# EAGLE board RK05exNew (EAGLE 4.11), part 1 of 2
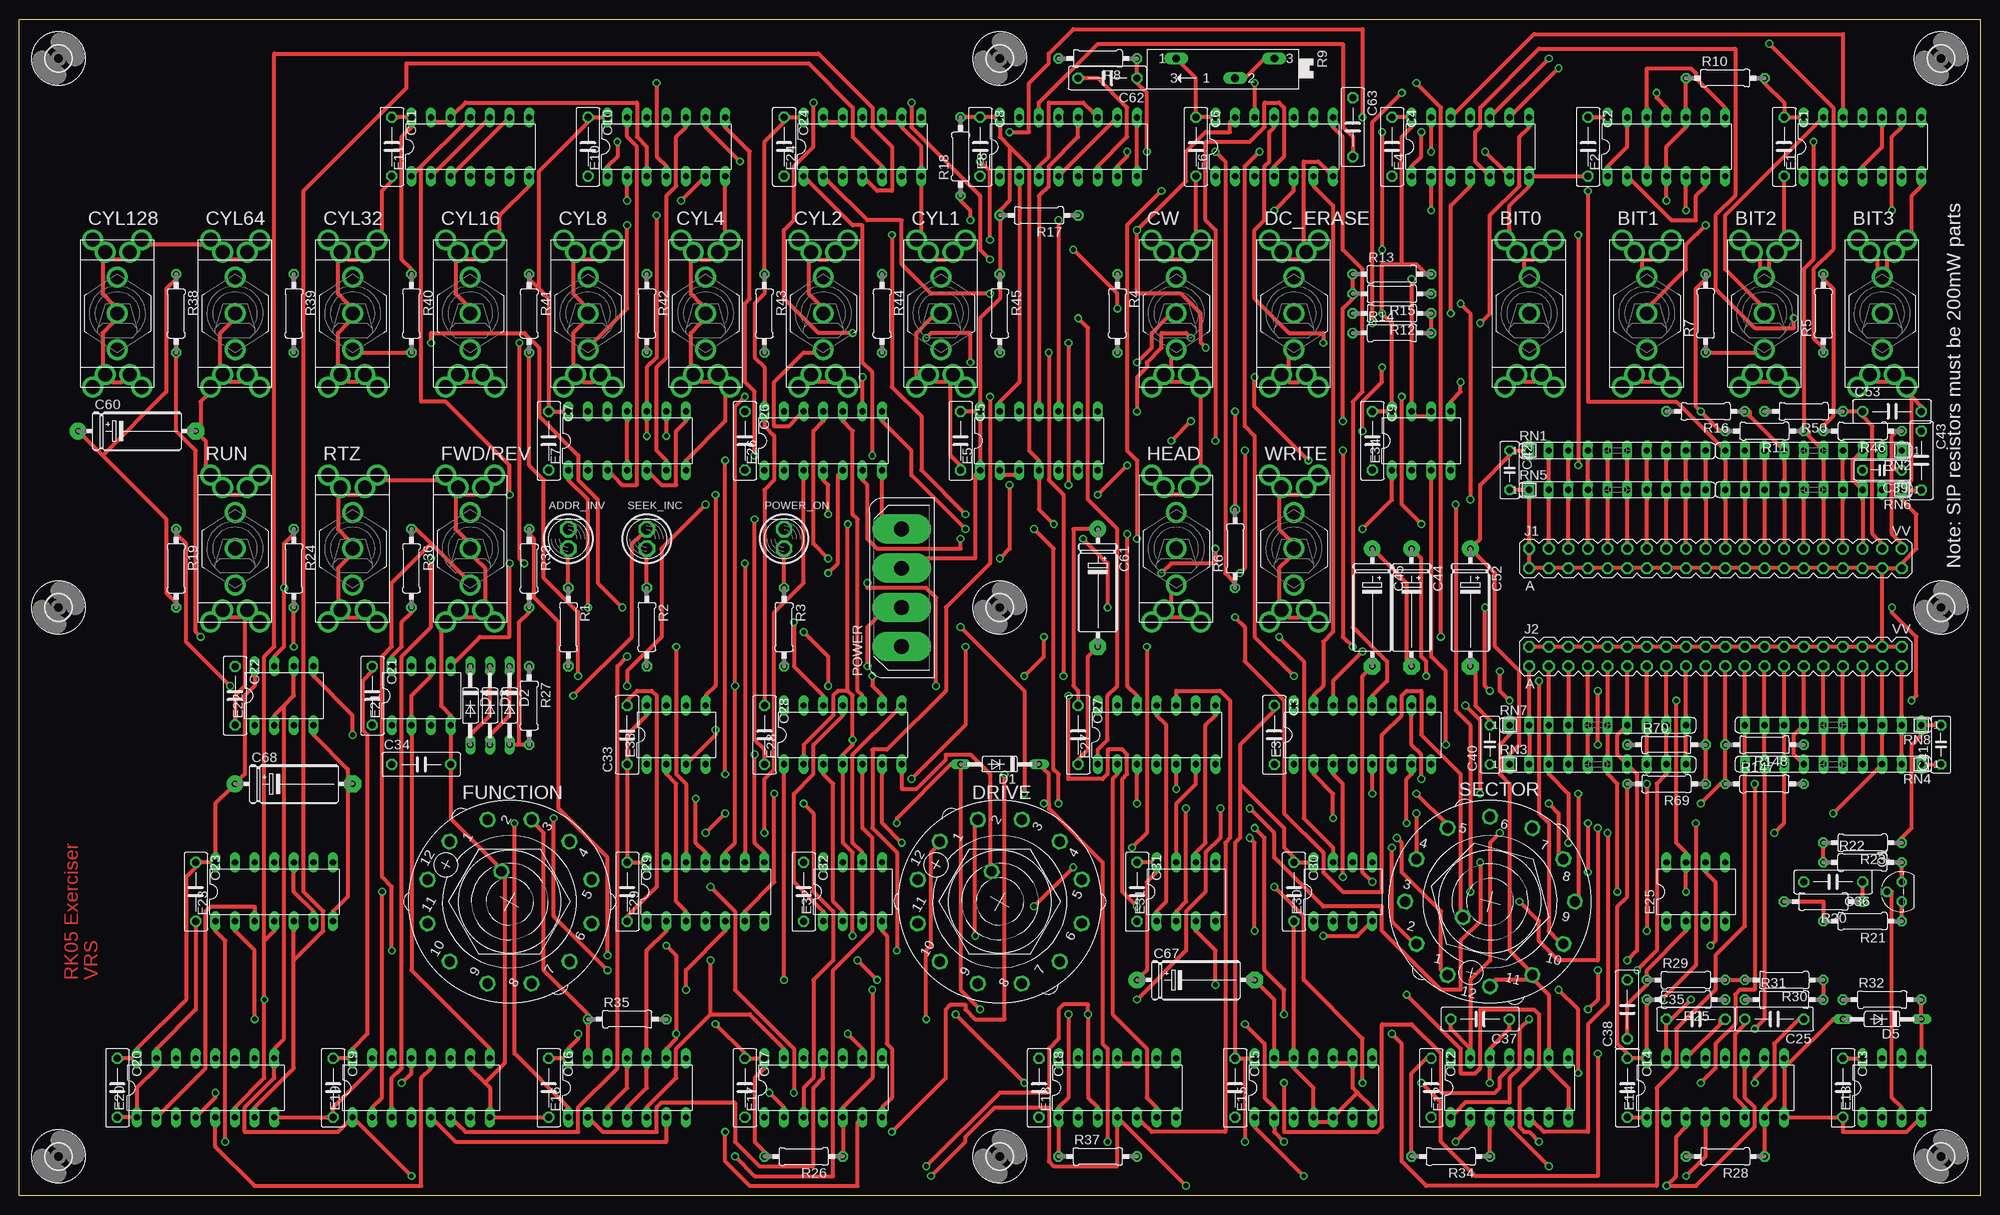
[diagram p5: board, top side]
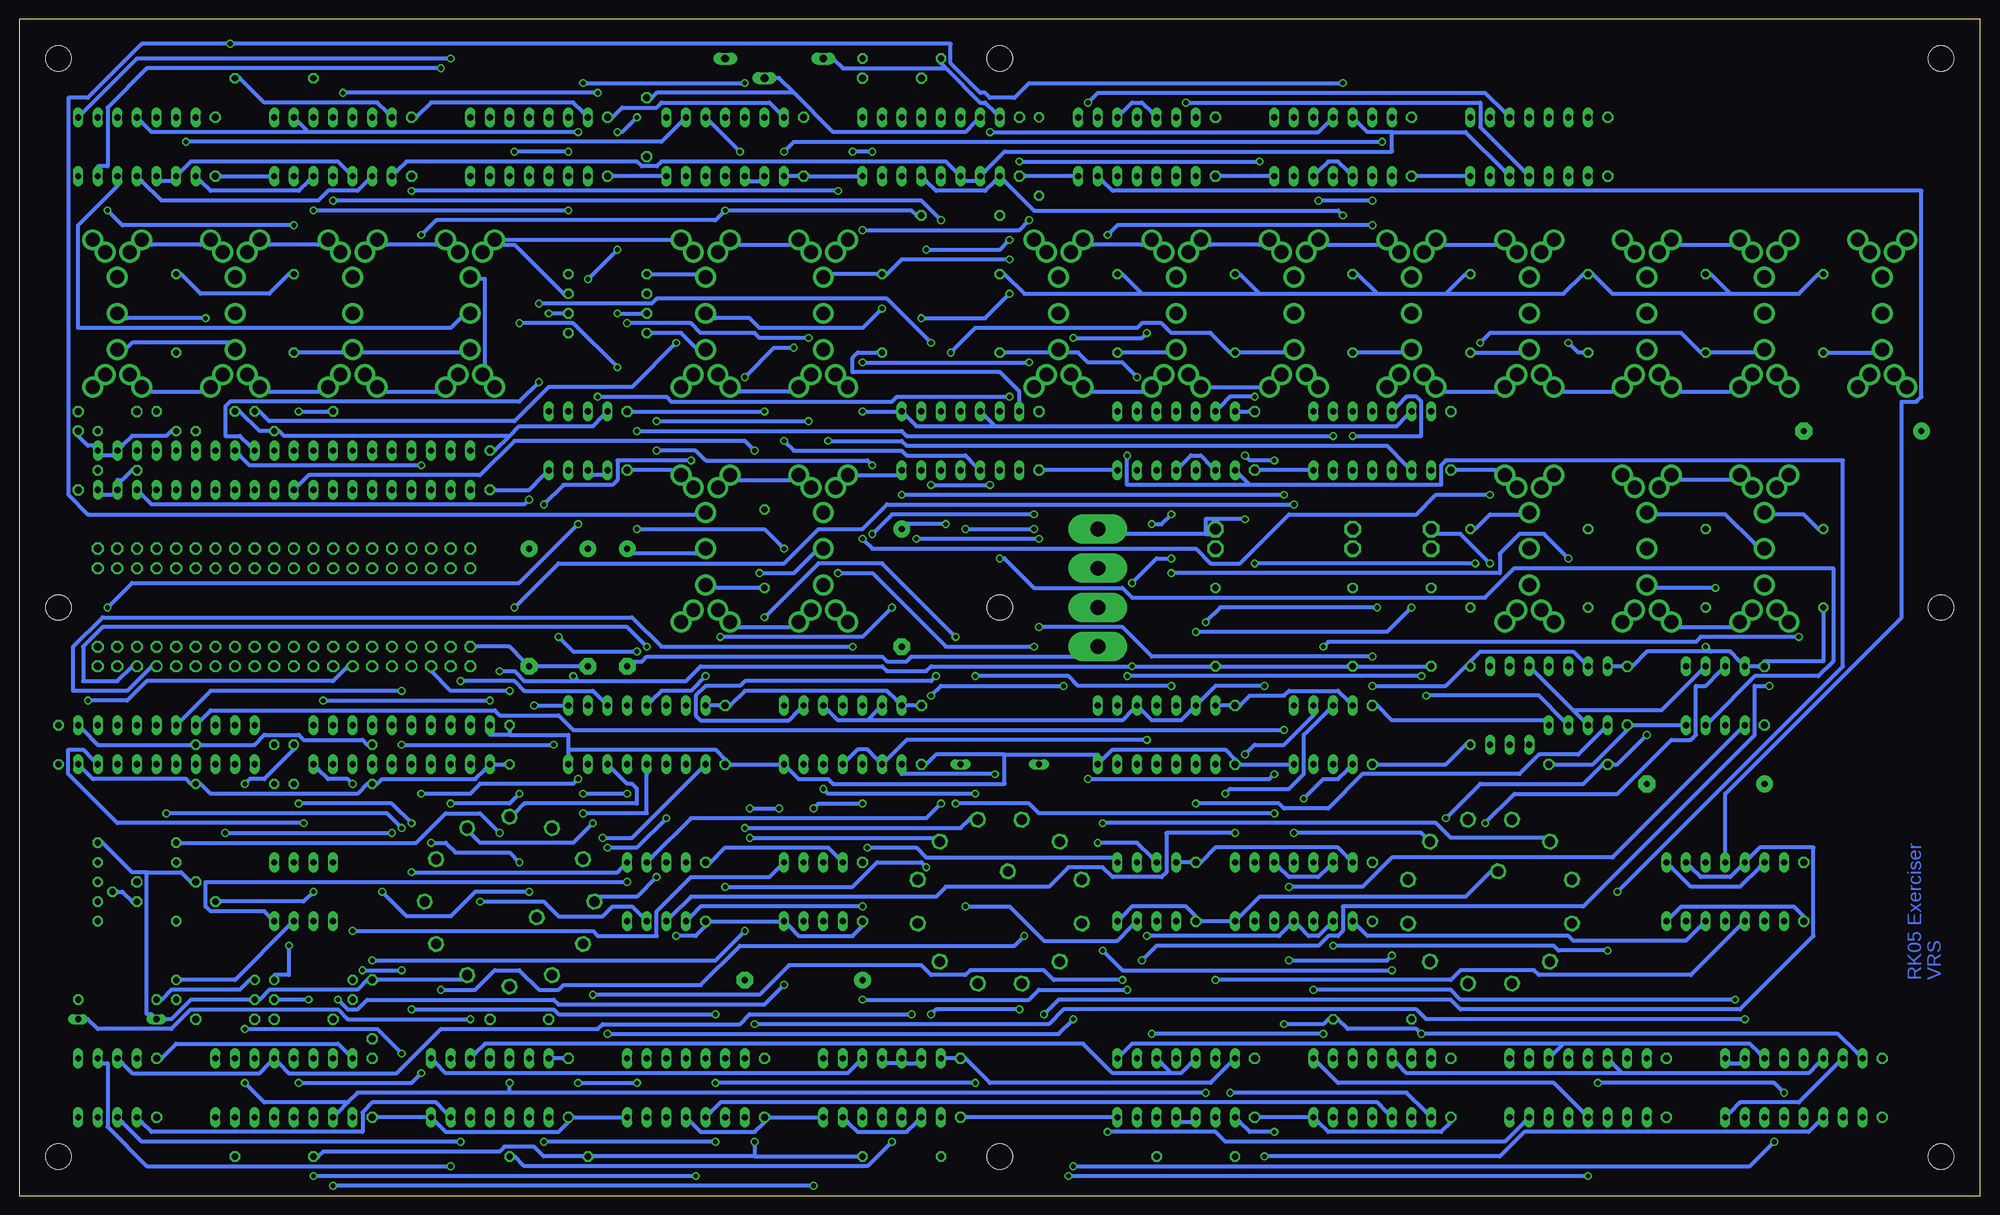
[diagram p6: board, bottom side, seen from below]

Size 254 x 152.4 mm. Coordinates in mm from the lower left corner, seen from the top.
Outline: 0,0 0,152.4 254,152.4 254,0 0,0
Copper layers (1*16): Top 0.035mm / dielectric 1.5mm / Bottom 0.035mm
Design rules "10mils": minimum track width 10mil, minimum drill 24mil, track to track 10mil, track to pad 10mil, pad to pad 10mil, via to via 10mil, smd to smd 0mil, copper to edge 25mil, drill to drill 10mil, minimum pad ring 10mil, minimum via ring 8mil, stop-mask expansion 0mil, vias tented up to drill 0mil, thermal gap 10mil
Net classes: 0 default: width 0.508 mm, drill 0.279 mm

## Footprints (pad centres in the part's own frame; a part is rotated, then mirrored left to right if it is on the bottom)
BULB = drill 1.422 octagon: A 0,0; B 0,2.54
7109MD9V3 = drill 1.803 round: 1 0,4.699; 2 0,0; 3 0,-4.699; NC@1 -3.175,9.525; NC@2 -1.587,7.938; NC@3 3.175,9.525; NC@4 1.587,7.938; NC@5 -3.175,-9.525; NC@6 -1.587,-7.938; NC@7 1.587,-7.938; NC@8 3.175,-9.525
C075-032X103 = drill 0.914 octagon: 1 -3.81,0; 2 3.81,0
C050-025X075 = drill 0.813 octagon: 1 -2.54,0; 2 2.54,0
E15-5 = drill 0.813 pad 2.159 round: + -7.62,0 | drill 0.813 pad 2.159 octagon: - 7.62,0
DO35-10 = drill 0.813 long: A 5.08,0; C -5.08,0
DO35Z10 = drill 0.813 long: A 5.08,0; C -5.08,0
CK101X12 = drill 1.321 octagon: 1 -2.845,-10.617; 2 -7.772,-7.772; 3 -10.617,-2.845; 4 -10.617,2.845; 5 -7.772,7.772; 6 -2.845,10.617; 7 2.845,10.617; 8 7.772,7.772; 9 10.617,2.845; 10 10.617,-2.845; 11 7.772,-7.772; 12 2.845,-10.617; A -2.87,-2.87
DIL14 = drill 0.813 long: 1 -7.62,-3.81; 2 -5.08,-3.81; 3 -2.54,-3.81; 4 0,-3.81; 5 2.54,-3.81; 6 5.08,-3.81; 7 7.62,-3.81; 8 7.62,3.81; 9 5.08,3.81; 10 2.54,3.81; 11 0,3.81; 12 -2.54,3.81; 13 -5.08,3.81; 14 -7.62,3.81
DIL16 = drill 0.813 long: 1 -8.89,-3.81; 2 -6.35,-3.81; 3 -3.81,-3.81; 4 -1.27,-3.81; 5 1.27,-3.81; 6 3.81,-3.81; 7 6.35,-3.81; 8 8.89,-3.81; 9 8.89,3.81; 10 6.35,3.81; 11 3.81,3.81; 12 1.27,3.81; 13 -1.27,3.81; 14 -3.81,3.81; 15 -6.35,3.81; 16 -8.89,3.81
DIL08 = drill 0.813 long: 1 -3.81,-3.81; 2 -1.27,-3.81; 3 1.27,-3.81; 4 3.81,-3.81; 5 3.81,3.81; 6 1.27,3.81; 7 -1.27,3.81; 8 -3.81,3.81
DEC40PINV = drill 1.016 octagon: A -24.13,-1.27; AA 3.81,-1.27; B -24.13,1.27; BB 3.81,1.27; C -21.59,-1.27; CC 6.35,-1.27; D -21.59,1.27; DD 6.35,1.27; E -19.05,-1.27; EE 8.89,-1.27; F -19.05,1.27; FF 8.89,1.27; H -16.51,-1.27; HH 11.43,-1.27; J -16.51,1.27; JJ 11.43,1.27; K -13.97,-1.27; KK 13.97,-1.27; L -13.97,1.27; LL 13.97,1.27; M -11.43,-1.27; MM 16.51,-1.27; N -11.43,1.27; NN 16.51,1.27; P -8.89,-1.27; PP 19.05,-1.27; R -8.89,1.27; RR 19.05,1.27; S -6.35,-1.27; SS 21.59,-1.27; T -6.35,1.27; TT 21.59,1.27; U -3.81,-1.27; UU 24.13,-1.27; V -3.81,1.27; VV 24.13,1.27; W -1.27,-1.27; X -1.27,1.27; Y 1.27,-1.27; Z 1.27,1.27
FLOPPY-4 = drill 1.93 pad 3.81 long: 1 7.62,0; 2 2.54,0; 3 -2.54,0; 4 -7.62,0
TO92E = drill 0.813 octagon: B1 -1.27,0; B2 1.27,0; E 0,1.905
0207/10 = drill 0.813 octagon: 1 -5.08,0; 2 5.08,0
SP19L = drill 1.016 long: A 5.715,-1.27; E -6.985,-1.27; S -1.905,1.27
SIL10 = drill 0.813 long: 1 -11.43,0; 2 -8.89,0; 3 -6.35,0; 4 -3.81,0; 5 -1.27,0; 6 1.27,0; 7 3.81,0; 8 6.35,0; 9 8.89,0; 10 11.43,0
3,3 = hole 3.3: 0,0

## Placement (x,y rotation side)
ADDR_INV  [BULB]  71.12,83.82 0 top
BIT0  7101  [7109MD9V3]  195.58,114.3 0 top
BIT1  7101  [7109MD9V3]  210.82,114.3 0 top
BIT2  7101  [7109MD9V3]  226.06,114.3 0 top
BIT3  7101  [7109MD9V3]  241.3,114.3 0 top
C1  .01uf  [C075-032X103]  228.6,135.89 270 top
C2  .01uf  [C075-032X103]  203.2,135.89 270 top
C3  .01uf  [C075-032X103]  162.56,59.69 270 top
C4  .01uf  [C075-032X103]  177.8,135.89 270 top
C5  .01uf  [C075-032X103]  121.92,97.79 270 top
C6  .01uf  [C075-032X103]  152.4,135.89 270 top
C7  .01uf  [C075-032X103]  68.58,97.79 270 top
C8  .01uf  [C075-032X103]  124.46,135.89 270 top
C9  .01uf  [C075-032X103]  175.26,97.79 270 top
C10  .01uf  [C075-032X103]  73.66,135.89 270 top
C11  .01uf  [C075-032X103]  48.26,135.89 270 top
C12  .01uf  [C075-032X103]  182.88,13.97 270 top
C13  .01uf  [C075-032X103]  236.22,13.97 270 top
C14  .01uf  [C075-032X103]  208.28,13.97 270 top
C15  .01uf  [C075-032X103]  157.48,13.97 270 top
C16  .01uf  [C075-032X103]  68.58,13.97 270 top
C17  .01uf  [C075-032X103]  93.98,13.97 270 top
C18  .01uf  [C075-032X103]  132.08,13.97 270 top
C19  .01uf  [C075-032X103]  40.64,13.97 270 top
C20  .01uf  [C075-032X103]  12.7,13.97 270 top
C21  .01uf  [C075-032X103]  45.72,64.77 270 top
C22  .01uf  [C075-032X103]  27.94,64.77 270 top
C23  .01uf  [C075-032X103]  22.86,39.37 270 top
C24  .01uf  [C075-032X103]  99.06,135.89 270 top
C25  470pf  [C075-032X103]  227.33,22.86 180 top
C26  .01uf  [C075-032X103]  93.98,97.79 270 top
C27  .01uf  [C075-032X103]  137.16,59.69 270 top
C28  .01uf  [C075-032X103]  96.52,59.69 270 top
C29  .01uf  [C075-032X103]  78.74,39.37 270 top
C30  .01uf  [C075-032X103]  165.1,39.37 270 top
C31  .01uf  [C075-032X103]  144.78,39.37 270 top
C32  .01uf  [C075-032X103]  101.6,39.37 270 top
C33  .01uf  [C075-032X103]  78.74,59.69 90 top
C34  .001uf  [C075-032X103]  52.07,55.88 0 top
C35  470pf  [C075-032X103]  217.17,22.86 0 top
C36  .033uf  [C075-032X103]  234.95,40.64 180 top
C37  .001uf  [C075-032X103]  189.23,22.86 180 top
C38  100pf  [C075-032X103]  208.28,24.13 90 top
C39  .001  [C050-025X075]  241.3,93.98 180 top
C40  .22uf  [C050-025X075]  190.5,58.42 90 top
C41  .22uf  [C050-025X075]  248.92,58.42 90 top
C42  .22uf  [C050-025X075]  193.04,93.98 270 top
C43  .22uf  [C075-032X103]  246.38,95.25 270 top
C44  6.8uf  [E15-5]  180.34,76.2 270 top
C45  6.8uf  [E15-5]  175.26,76.2 270 top
C52  39uf  [E15-5]  187.96,76.2 270 top
C53  .001  [C075-032X103]  242.57,101.6 0 top
C60  6.8uf  [E15-5]  15.24,99.06 0 top
C61  6.8uf  [E15-5]  139.7,78.74 270 top
C62  27pf  [C075-032X103]  140.97,144.78 180 top
C63  47pf  [C075-032X103]  172.72,138.43 270 top
C67  6.8uf  [E15-5]  152.4,27.94 0 top
C68  6.8uf  [E15-5]  35.56,53.34 0 top
CW  7101  [7109MD9V3]  149.86,114.3 0 top
CYL1  7101  [7109MD9V3]  119.38,114.3 0 top
CYL2  7101  [7109MD9V3]  104.14,114.3 0 top
CYL4  7101  [7109MD9V3]  88.9,114.3 0 top
CYL8  7101  [7109MD9V3]  73.66,114.3 0 top
CYL16  7101  [7109MD9V3]  58.42,114.3 0 top
CYL32  7101  [7109MD9V3]  43.18,114.3 0 top
CYL64  7101  [7109MD9V3]  27.94,114.3 0 top
CYL128  7101  [7109MD9V3]  12.7,114.3 0 top
D1  D664  [DO35-10]  127,55.88 180 top
D2  D664  [DO35-10]  63.5,63.5 270 top
D3  D664  [DO35-10]  60.96,63.5 270 top
D4  D664  [DO35-10]  58.42,63.5 270 top
D5  1N746  [DO35Z10]  241.3,22.86 180 top
DC_ERASE  7101  [7109MD9V3]  165.1,114.3 0 top
DRIVE  [CK101X12]  127,38.1 240 top
E1  74LS10N  [DIL14]  238.76,135.89 0 top
E2  74LS74N  [DIL14]  213.36,135.89 0 top
E3  74LS42N  [DIL16]  173.99,59.69 0 top
E4  74LS20N  [DIL14]  187.96,135.89 0 top
E5  74LS74N  [DIL14]  132.08,97.79 0 top
E6  74LS04N  [DIL14]  162.56,135.89 0 top
E7  74LS00N  [DIL14]  78.74,97.79 0 top
E8  74123N  [DIL16]  135.89,135.89 0 top
E10  74LS00N  [DIL14]  83.82,135.89 0 top
E11  74LS74N  [DIL14]  58.42,135.89 0 top
E12  74LS04N  [DIL14]  193.04,13.97 0 top
E13  DS75451N  [DIL08]  242.57,13.97 0 top
E14  74123N  [DIL16]  219.71,13.97 0 top
E15  74LS00N  [DIL14]  167.64,13.97 0 top
E16  74LS10N  [DIL14]  78.74,13.97 0 top
E17  74LS00N  [DIL14]  104.14,13.97 0 top
E18  74LS74N  [DIL14]  142.24,13.97 0 top
E19  74LS193N  [DIL16]  52.07,13.97 0 top
E20  74LS193N  [DIL16]  24.13,13.97 0 top
E21  DS75451N  [DIL08]  52.07,64.77 0 top
E22  DS75451N  [DIL08]  34.29,64.77 0 top
E23  74LS10N  [DIL14]  33.02,39.37 0 top
E24  74LS20N  [DIL14]  109.22,135.89 0 top
E25  LM741P  [DIL08]  217.17,39.37 0 top
E26  74LS00N  [DIL14]  104.14,97.79 0 top
E27  74LS00N  [DIL14]  147.32,59.69 0 top
E28  74LS00N  [DIL14]  106.68,59.69 0 top
E29  74LS00N  [DIL14]  88.9,39.37 0 top
E30  DS75451N  [DIL08]  171.45,39.37 0 top
E31  DS75451N  [DIL08]  151.13,39.37 0 top
E32  DS75451N  [DIL08]  107.95,39.37 0 top
E33  DS75451N  [DIL08]  85.09,59.69 0 top
E34  DS75451N  [DIL08]  181.61,97.79 0 top
FUNCTION  [CK101X12]  63.5,38.1 240 top
FWD/REV  7101  [7109MD9V3]  58.42,83.82 0 top
HEAD  7101  [7109MD9V3]  149.86,83.82 0 top
J1  DEC40PINSV  [DEC40PINV]  219.71,82.55 0 top
J2  DEC40PINSV  [DEC40PINV]  219.71,69.85 0 top
POWER  [FLOPPY-4]  114.3,78.74 90 top
POWER_ON  [BULB]  99.06,83.82 0 top
Q1  2N4894  [TO92E]  243.84,39.37 90 top
R1  0ohm  [0207/10]  71.12,73.66 270 top
R2  0ohm  [0207/10]  81.28,73.66 270 top
R3  0ohm  [0207/10]  99.06,73.66 270 top
R4  1K  [0207/10]  142.24,114.3 270 top
R5  56K  [0207/10]  233.68,114.3 90 top
R6  56K  [0207/10]  157.48,83.82 90 top
R7  1K  [0207/10]  218.44,114.3 90 top
R8  5.6k  [0207/10]  139.7,147.32 180 top
R9  10K  [SP19L]  155.57,146.05 180 top
R10  1K  [0207/10]  220.98,144.78 0 top
R11  1K  [0207/10]  226.06,99.06 180 top
R12  330  [0207/10]  177.8,114.3 180 top
R13  330  [0207/10]  177.8,119.38 0 top
R14  750  [0207/10]  177.8,111.76 0 top
R15  750  [0207/10]  177.8,116.84 180 top
R16  1K  [0207/10]  218.44,101.6 180 top
R17  1K  [0207/10]  132.08,127 180 top
R18  1K  [0207/10]  121.92,134.62 90 top
R19  1K  [0207/10]  20.32,81.28 270 top
R20  470K  [0207/10]  233.68,38.1 180 top
R21  330  [0207/10]  238.76,35.56 180 top
R22  120  [0207/10]  238.76,43.18 0 top
R23  68  [0207/10]  238.76,45.72 180 top
R24  1K  [0207/10]  35.56,81.28 270 top
R25  10K  [0207/10]  215.9,25.4 180 top
R26  1K  [0207/10]  101.6,5.08 180 top
R27  1K  [0207/10]  66.04,63.5 270 top
R28  22K  [0207/10]  220.98,5.08 180 top
R29  100K  [0207/10]  215.9,27.94 0 top
R30  100K  [0207/10]  228.6,27.94 180 top
R31  1M  [0207/10]  228.6,25.4 0 top
R32  1K  [0207/10]  241.3,25.4 0 top
R33  1K  [0207/10]  66.04,81.28 270 top
R34  1K  [0207/10]  185.42,5.08 180 top
R35  1K  [0207/10]  78.74,22.86 0 top
R36  1K  [0207/10]  50.8,81.28 270 top
R37  1K  [0207/10]  139.7,5.08 0 top
R38  1K  [0207/10]  20.32,114.3 270 top
R39  1K  [0207/10]  35.56,114.3 270 top
R40  1K  [0207/10]  50.8,114.3 270 top
R41  1K  [0207/10]  66.04,114.3 270 top
R42  1K  [0207/10]  81.28,114.3 270 top
R43  1K  [0207/10]  96.52,114.3 270 top
R44  1K  [0207/10]  111.76,114.3 270 top
R45  1K  [0207/10]  127,114.3 270 top
R46  390  [0207/10]  238.76,99.06 180 top
R50  390  [0207/10]  231.14,101.6 180 top
R69  180  [0207/10]  213.36,53.34 180 top
R70  390  [0207/10]  213.36,58.42 0 top
R147  180  [0207/10]  226.06,53.34 0 top
R148  390  [0207/10]  226.06,58.42 180 top
RN1  180  [SIL10]  207.01,96.52 0 top
RN2  180  [SIL10]  232.41,96.52 180 top
RN3  180  [SIL10]  204.47,55.88 0 top
RN4  180  [SIL10]  234.95,55.88 180 top
RN5  390  [SIL10]  207.01,91.44 0 top
RN6  390  [SIL10]  232.41,91.44 180 top
RN7  390  [SIL10]  204.47,60.96 0 top
RN8  390  [SIL10]  234.95,60.96 180 top
RTZ  7101  [7109MD9V3]  43.18,83.82 0 top
RUN  7101  [7109MD9V3]  27.94,83.82 0 top
SECTOR  [CK101X12]  190.5,38.1 345 top
SEEK_INC  [BULB]  81.28,83.82 0 top
U$1  [3,3]  5.08,147.32 0 top
U$2  [3,3]  5.08,5.08 0 top
U$3  [3,3]  5.08,76.2 0 top
U$4  [3,3]  248.92,147.32 0 top
U$5  [3,3]  248.92,5.08 0 top
U$6  [3,3]  248.92,76.2 0 top
U$7  [3,3]  127,147.32 0 top
U$8  [3,3]  127,5.08 0 top
U$9  [3,3]  127,76.2 0 top
WRITE  7108  [7109MD9V3]  165.1,83.82 0 top

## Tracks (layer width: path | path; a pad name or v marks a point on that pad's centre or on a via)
0BIT  (via drill 0.61)
  Top 0.508: v199.39,146.05 193.68,140.34 E4.9
  Bottom 0.508: v199.39,146.05 237.49,146.05 242.57,140.97 242.57,133.35 243.84,133.35 E1.6
1.44MHZ
  Top 0.508: E5.11 132.08,102.87 132.08,129.54 133.35,130.81 133.35,133.35 137.16,137.16 137.16,138.43 E8.12
1BIT  (via drill 0.61)
  Top 0.508: v198.12,147.32 191.13,140.34 E4.10
  Bottom 0.508: v198.12,147.32 238.76,147.32 245.75,140.34 E1.8
1L  (via drill 0.61)
  Top 0.508: v212.09,142.88 212.09,142.24 213.36,140.97 E2.11 | v179.07,142.88 175.26,139.06 v175.26,113.03 | v151.76,111.12 151.13,111.76 147.96,111.76 147.96,109.86 146.05,107.95 146.05,107.31 144.78,106.05 v144.78,101.6
  Bottom 0.508: 127.64,99.69 75.56,99.69 74.3,100.97 E7.13 | 127.64,99.69 128.91,100.97 E5.12 | 127.64,99.69 137.79,99.69 139.06,100.97 E5.8 140.34,101.6 v144.78,101.6 | v179.07,142.88 v212.09,142.88 | v175.26,113.03 167,113.03 165.74,111.76 158.75,111.76 158.12,111.12 v151.76,111.12
2.88MHZ
  Top 0.508: E8.4 135.25,132.72 141.6,139.06 E8.10
2BIT
  Top 0.508: E4.12 186.06,140.34 196.22,150.5 236.22,150.5 236.22,140.97 E1.12
2H  (via drill 0.61)
  Top 0.508: v181.61,137.79 181.61,134.62 180.34,133.35 E4.1
  Bottom 0.508: v181.61,137.79 216.53,137.79 | 216.53,137.79 217.81,139.06 E2.9 | 216.53,137.79 236.85,137.79 238.12,139.06 E1.11
2L
  Top 0.508: E2.3 210.82,133.35 210.82,138.43 E2.12 210.82,140.97 210.82,146.05 216.53,146.05 217.17,145.41 217.17,144.78 220.98,140.97 E2.8
  Bottom 0.508: E1.3 235.59,131.44 234.31,131.44 E1.2 233.04,132.72 231.78,133.99 212.72,133.99 211.46,132.72 E2.3
3BIT  (via drill 0.61)
  Top 0.508: v182.88,135.25 182.88,138.43 E4.13 | v189.87,135.25 192.41,132.72 E4.6
  Bottom 0.508: v182.88,135.25 v189.87,135.25
4H  (via drill 0.61)
  Top 0.508: v182.88,127.64 182.88,130.81 E4.2 | v215.9,127.64 215.9,130.81 E2.5
  Bottom 0.508: v182.88,127.64 v215.9,127.64 | E1.1 230.5,131.44 229.24,130.18 217.81,130.18 216.53,131.44 E2.5
4L
  Top 0.508: E1.4 238.76,133.35 241.3,135.89 241.3,138.43 E1.10 | E2.2 208.91,131.44 214,126.36 217.17,126.36 217.17,129.54 218.44,130.81 E2.6
  Bottom 0.508: E1.4 238.12,131.44 235.59,128.91 215.26,128.91 214,130.18 210.19,130.18 208.91,131.44 E2.2
202_DETECT_L
  Bottom 0.508: E23.11 33.02,44.45 33.02,52.07 10.16,74.93 10.16,102.87 8.26,102.87 7.62,103.5 7.62,130.18 112.39,130.18 113.67,131.44 E24.6
+3V  (via drill 0.61)
  Top 0.508: 34.29,63.5 35.56,64.77 35.56,67.31 E22.6 | 34.29,63.5 33.02,62.23 E22.2 | E19.9 60.96,19.05 50.8,29.21 50.8,59.69 E21.2 50.8,62.23 50.8,64.77 53.34,67.31 E21.6 | 34.29,63.5 34.29,20.32 33.02,19.05 E20.9 33.02,16.51 33.02,15.24 29.21,11.43 29.21,8.26 41.27,8.26 42.55,9.53 E19.1 43.81,9.53 v50.8,2.54 | v151.13,1.27 142.88,9.53 E18.4 142.24,8.89 142.24,3.81 133.99,3.81 133.35,4.45 133.35,11.43 126.36,11.43 122.56,7.62 122.56,6.99 v118.11,2.54 | E14.3 215.9,8.89 214.63,7.62 214.63,2.54 v213.36,1.27 217.17,1.27 224.79,8.89 224.79,11.43 223.52,12.7 223.52,16.51 E14.11
  Bottom 0.508: E20.10 31.11,17.14 32.38,17.14 E20.9 | 52.7,62.87 51.44,61.59 E21.2 | 52.7,62.87 57.78,67.94 D4.C | 52.7,62.87 41.27,62.87 36.2,67.94 E22.6 | v151.13,1.27 v213.36,1.27 | v50.8,2.54 v118.11,2.54
+3VA  (via drill 0.61)
  Top 0.508: v151.76,100.33 v149.22,97.79 | v171.45,100.33 171.45,114.94 172.72,116.2 R15.2 172.72,117.47 172.72,118.75 R13.1
  Bottom 0.508: v149.22,97.79 139.7,97.79 139.06,97.16 76.83,97.16 74.3,94.61 E7.2 | v171.45,100.33 v151.76,100.33 | DC_ERASE.1 166.37,119.38 172.09,119.38 R13.1
+3VB  (via drill 0.61)
  Top 0.508: R14.2 182.88,112.39 182.88,113.67 R12.1 | v185.42,114.3 185.42,128.27 187.96,130.81 E4.4
  Bottom 0.508: v185.42,114.3 183.51,114.3 R12.1
+3VC  (via drill 0.61)
  Top 0.508: E11.2 53.98,132.72 60.33,139.06 E11.10 | v125.73,121.28 124.46,122.56 124.46,129.54 115.57,138.43 v115.57,141.6
  Bottom 0.508: CW.1 148.59,119.38 142.88,119.38 R4.1 141.6,119.38 139.7,121.28 v125.73,121.28 | v115.57,141.6 114.3,142.88 64.14,142.88 61.59,140.34 E11.10
+15V  (via drill 0.61)
  Top 0.508: R20.2 229.24,38.1 233.68,38.1 233.68,36.2 R21.2 | v215.9,39.37 215.9,41.91 E25.7 215.9,44.45 214.63,45.72 v214.63,64.14 | v182.25,67.31 182.25,69.22 181.61,69.85 181.61,82.55 180.97,83.19 C44.+ | v109.86,68.58 109.86,73.66 111.12,74.93 POWER.3 | v193.04,64.14 191.77,65.41 v191.77,67.94
  Bottom 0.508: v215.9,39.37 217.17,38.1 227.97,38.1 R20.2 | R1.2 71.75,68.58 80.64,68.58 R2.2 81.92,68.58 98.42,68.58 R3.2 99.69,68.58 v109.86,68.58 135.89,68.58 136.53,67.94 141.6,67.94 142.24,68.58 165.74,68.58 167.64,66.67 181.61,66.67 | 181.61,66.67 v182.25,67.31 | v214.63,64.14 v193.04,64.14 | v191.77,67.94 189.87,67.94 188.59,66.67 181.61,66.67
-15V  (via drill 0.61)
  Top 0.508: v175.26,40.64 173.99,41.91 173.99,67.31 174.62,67.94 C45.-
  Bottom 0.508: v175.26,40.64 229.87,40.64 229.87,37.47 229.24,36.83 222.25,36.83 221.62,36.2 E25.4 | POWER.4 117.47,69.85 138.43,69.85 139.06,69.22 141.6,69.22 142.24,69.85 172.72,69.85 173.35,69.22 174.62,69.22 C45.-
ADDR_COUNTER_1  (via drill 0.61)
  Top 0.508: v53.34,82.55 53.34,73.66 49.53,69.85 49.53,16.51 48.26,15.24 48.26,11.43 E19.3 | v104.78,80.64 106.05,81.92 106.05,93.34 E26.5
  Bottom 0.508: v53.34,82.55 56.52,85.72 59.69,85.72 62.23,83.19 62.23,80.64 v104.78,80.64
ADDR_COUNTER_2  (via drill 0.61)
  Top 0.508: v46.99,39.37 46.99,12.7 45.72,11.43 E19.2 | v110.49,95.89 110.49,106.68 109.22,107.95 109.22,125.73 107.95,125.73 102.23,131.44 E24.1
  Bottom 0.508: v46.99,39.37 17.78,68.58 17.78,95.25 69.22,95.25 69.85,94.61 69.85,92.08 94.61,92.08 | 94.61,92.08 95.89,93.34 E26.1 | v110.49,95.89 110.49,92.08 94.61,92.08
ADDR_COUNTER_4  (via drill 0.61)
  Top 0.508: v78.74,69.85 77.47,68.58 77.47,16.51 72.39,11.43 72.39,8.26 57.78,8.26 56.52,9.53 E19.6 | v121.92,73.66 130.18,65.41 v130.18,52.07 | v149.86,52.7 149.86,54.61 E27.5
  Bottom 0.508: v78.74,69.85 107.31,69.85 111.12,73.66 v121.92,73.66 | v130.18,52.07 149.22,52.07 v149.86,52.7
ADDR_COUNTER_8  (via drill 0.61)
  Top 0.508: v113.03,8.26 120.02,15.24 120.02,24.13 120.65,24.77 122.56,24.77 122.56,24.13 123.83,22.86 127.64,22.86 v127.64,54.61 | v125.73,116.84 118.11,116.84 114.3,120.65 114.3,126.36 109.86,126.36 104.78,131.44 E24.2 | v137.16,113.67 138.43,112.39 138.43,90.17 142.24,86.36 142.24,66.04 140.97,64.77 140.97,59.05 139.7,57.78 139.7,57.15 E27.1
  Bottom 0.508: v113.03,8.26 99.06,8.26 97.79,6.99 61.59,6.99 59.05,9.53 E19.7 | v127.64,54.61 139.7,54.61 E27.1 | v125.73,116.84 128.91,113.67 v137.16,113.67
ADDR_COUNTER_16  (via drill 0.61)
  Top 0.508: v92.71,5.08 95.25,2.54 105.41,2.54 105.41,29.21 110.49,34.29 110.49,46.35 109.22,47.62 109.22,54.61 E28.5
  Bottom 0.508: v92.71,5.08 62.23,5.08 59.05,8.26 22.23,8.26 20.95,9.53 E20.3
ADDR_COUNTER_32  (via drill 0.61)
  Top 0.508: E20.2 18.41,10.79 24.13,16.51 24.13,36.83 24.77,37.47 30.48,37.47 30.48,36.83 E23.3 | v99.06,27.94 99.06,54.61 E28.1
  Bottom 0.508: v99.06,27.94 68.58,27.94 67.31,29.21 57.78,29.21 57.15,28.57 37.47,28.57 31.11,34.92 E23.3
ADDR_COUNTER_64  (via drill 0.61)
  Top 0.508: 31.75,33.02 v31.75,25.4 31.75,15.24 27.94,11.43 E20.6 | 31.75,33.02 33.02,34.29 E23.4 | v86.36,26.67 86.36,29.21 91.44,34.29 E29.5 | 31.75,33.02 31.75,69.85 33.02,71.12 33.02,147.96 103.5,147.96 110.49,140.97 110.49,138.43 113.03,135.89 113.03,130.18 111.12,130.18 109.86,131.44 E24.4
  Bottom 0.508: v86.36,26.67 68.58,26.67 67.31,25.4 v31.75,25.4
ADDR_COUNTER_128
  Top 0.508: 35.56,30.48 35.56,34.29 E23.5 | 35.56,30.48 35.56,16.51 30.48,11.43 E20.7 | 35.56,30.48 39.37,34.29 39.37,36.83 36.83,39.37 36.83,130.18 50.16,143.51 50.16,146.69 102.23,146.69 107.95,140.97 107.95,137.16 111.76,133.35 E24.5
  Bottom 0.508: E29.1 80.64,34.92 79.38,33.66 53.34,33.66 52.7,33.02 38.1,33.02 36.2,34.92 E23.5
ADDR_SOURCE_H  (via drill 0.61)
  Top 0.508: v93.98,103.5 92.71,102.23 v92.71,66.04 92.71,45.72 91.44,44.45 E29.10 | E26.10 106.68,100.33 107.95,99.06 107.95,88.27 108.58,87.63 108.58,65.41 109.22,64.77 E28.10 | E18.5 145.41,9.53 146.69,8.26 156.21,8.26 156.21,45.72 156.84,46.35 156.84,64.14 155.57,65.41 149.86,65.41 149.86,64.77 E27.10
  Bottom 0.508: E29.13 84.45,42.55 85.72,41.27 89.53,41.27 90.81,42.55 E29.10 | v93.98,103.5 97.16,103.5 98.42,102.23 E26.13 | 144.15,61.59 142.88,62.87 E27.13 | 144.15,61.59 147.96,61.59 149.22,62.87 E27.10 | 144.15,61.59 111.12,61.59 109.86,62.87 E28.10 108.58,62.87 107.31,61.59 103.5,61.59 102.23,62.87 E28.13 100.97,64.14 99.06,66.04 v92.71,66.04
ADDR_SOURCE_L  (via drill 0.61)
  Top 0.508: E27.2 142.24,54.61 141.6,53.98 141.6,23.5 146.05,19.05 146.05,12.7 147.32,11.43 E18.6 | E16.4 78.74,11.43 81.28,13.97 81.28,16.51 E16.10 81.28,19.05 81.28,31.75 83.82,34.29 E29.2 | 107.31,65.41 106.05,65.41 105.41,64.77 105.41,62.23 101.6,58.42 101.6,57.15 E28.2 | 107.31,65.41 107.95,64.77 v107.95,59.05 107.95,58.42 106.68,57.15 E28.4 106.68,54.61 106.68,45.72 107.95,44.45 v107.95,33.66 | v104.78,88.27 104.78,92.08 104.14,92.71 E26.4 | 107.31,65.41 v107.31,87
  Bottom 0.508: E27.4 146.69,56.52 145.41,57.78 144.15,57.78 142.88,56.52 E27.2 141.6,56.52 139.06,59.05 v107.95,59.05 | E18.2 137.79,9.53 139.06,8.26 145.41,8.26 146.69,9.53 E18.6 | E29.2 84.45,34.92 85.72,33.66 87,33.66 88.27,34.92 E29.4 89.53,34.92 90.81,33.66 v107.95,33.66 | E26.2 99.69,94.61 100.97,95.89 102.23,95.89 103.5,94.61 E26.4 | v104.78,88.27 106.05,87 v107.31,87
ADDRESS_INVALID_L  (via drill 0.61)
  Top 0.508: v63.5,81.92 63.5,72.39 59.69,72.39 56.52,69.22 E21.5
  Bottom 0.508: v63.5,81.92 67.31,85.72 70.48,85.72 ADDR_INV.B
BIT_0L
  Bottom 0.508: E1.5 241.3,130.81 246.38,125.73 246.38,112.39 198.12,112.39 196.85,113.67 BIT0.2
BIT_1L  (via drill 0.61)
  Top 0.508: v242.57,127.64 242.57,137.16 243.84,138.43 E1.9 | v218.44,125.73 215.9,123.19 215.9,120.02 211.46,115.57 BIT1.2
  Bottom 0.508: v242.57,127.64 240.66,125.73 v218.44,125.73
BIT_2L
  Top 0.508: E1.13 233.04,139.06 220.98,127 220.98,120.02 225.43,115.57 BIT2.2
BIT_3L  (via drill 0.61)
  Top 0.508: v229.87,113.67 229.87,112.39 224.79,112.39 219.71,117.47 219.71,127 222.25,129.54 222.25,148.59 196.85,148.59 189.23,140.97 189.23,138.43 188.59,137.79 188.59,133.99 189.87,132.72 E4.5
  Bottom 0.508: v229.87,113.67 240.03,113.67 BIT3.2
BUS_AC_LO_L
  Top 0.508: 242.57,94.61 243.21,93.98 C39.1 | 242.57,94.61 242.57,98.42 243.21,99.06 R46.1 | 242.57,94.61 242.57,85.72 243.84,84.45 J1.VV
BUS_ADDR_ACCEPTED_L
  Top 0.508: RN3.5 203.2,57.15 203.2,59.69 RN7.5 203.2,62.23 203.2,67.94 J2.H
BUS_ADDRESS_INVALID_L  (via drill 0.61)
  Top 0.508: R26.1 106.68,5.71 106.68,8.89 E17.5 106.68,11.43 110.49,15.24 v110.49,26.67 | J2.C 198.12,67.94 198.12,62.23 RN7.3 198.12,59.69 198.12,57.15 RN3.3 198.12,54.61 200.66,52.07 v200.66,45.72 | v144.78,25.4 151.13,31.75 151.13,36.83 153.67,39.37 153.67,44.45 155.57,46.35 v155.57,50.16 | v159.38,50.16 162.56,46.99 162.56,43.81 168.91,37.47 176.53,37.47 176.53,34.29 184.15,26.67 186.69,26.67 186.69,33.02 189.23,35.56 v189.23,43.18
  Bottom 0.508: v110.49,26.67 121.92,26.67 123.19,25.4 v144.78,25.4 | v159.38,50.16 v155.57,50.16 | v189.23,43.18 190.5,44.45 197.49,44.45 198.75,45.72 v200.66,45.72
BUS_CA_00_L  (via drill 0.61)
  Top 0.508: v203.2,48.26 v203.2,41.91 | v217.81,50.8 220.34,53.34 R147.1 220.98,53.98 220.98,57.78 R148.2 220.98,59.05 220.98,67.94 J2.Y
  Bottom 0.508: v203.2,41.91 176.53,41.91 175.9,42.55 E30.5 | v203.2,48.26 205.74,50.8 v217.81,50.8
BUS_CA_01_L  (via drill 0.61)
  Top 0.508: v194.31,38.1 196.85,35.56 196.85,33.02 199.39,30.48 204.47,30.48 v204.47,47.62 | v234.95,49.53 240.66,55.24 RN4.3 241.3,57.15 241.3,59.69 RN8.3 241.3,62.23 241.3,67.94 J2.SS
  Bottom 0.508: v194.31,38.1 186.06,38.1 184.15,36.2 178.44,36.2 177.16,37.47 174.62,37.47 173.35,36.2 E30.3 | v204.47,47.62 206.38,49.53 v234.95,49.53
BUS_CA_02_L  (via drill 0.61)
  Top 0.508: v210.82,53.34 v210.82,34.29 | RN3.10 215.9,57.15 215.9,59.69 RN7.10 215.9,62.23 215.9,67.94 J2.U
  Bottom 0.508: v210.82,34.29 179.71,34.29 179.07,33.66 171.45,33.66 171.45,36.83 167,41.27 156.84,41.27 155.57,42.55 E31.5 | v210.82,53.34 211.46,53.98 214,53.98 215.26,55.24 RN3.10
BUS_CA_03_L  (via drill 0.61)
  Top 0.508: v154.94,27.3 154.94,31.75 152.4,34.29 E31.3 | v212.72,25.4 217.17,29.84 v217.17,48.26 | RN4.2 243.84,57.15 243.84,59.69 RN8.2 243.84,62.23 243.84,67.94 J2.UU
  Bottom 0.508: v154.94,27.3 157.48,24.77 184.15,24.77 184.78,25.4 208.91,25.4 210.19,24.13 211.46,24.13 v212.72,25.4 | v217.17,48.26 241.3,48.26 247.65,54.61 247.65,57.78 245.75,57.78 244.47,56.52 RN4.2
BUS_CA_04_L  (via drill 0.61)
  Top 0.508: RN4.5 236.22,57.15 236.22,59.69 RN8.5 236.22,62.23 236.22,67.94 J2.MM | v144.15,45.09 146.05,46.99 v146.05,71.12
  Bottom 0.508: v144.15,45.09 137.79,45.09 136.53,43.81 112.39,43.81 E32.5 | v146.05,71.12 170.81,71.12 174.62,74.93 243.21,74.93 247.01,71.12 247.01,65.41 240.03,65.41 236.85,68.58 J2.MM
BUS_CA_05_L  (via drill 0.61)
  Top 0.508: v136.53,42.55 v131.44,37.47 | v162.56,40.01 166.37,36.2 166.37,27.94 173.99,20.32 v173.99,14.61 | v181.61,14.61 184.15,12.06 184.15,6.99 188.59,2.54 204.47,2.54 v204.47,18.41 | v224.79,21.59 226.06,22.86 226.06,54.61 RN4.9 226.06,57.15 226.06,59.69 RN8.9 226.06,62.23 226.06,67.94 J2.CC
  Bottom 0.508: v131.44,37.47 125.73,37.47 121.28,33.02 111.76,33.02 109.86,34.92 E32.3 | v136.53,42.55 137.16,43.18 142.88,43.18 146.05,40.01 v162.56,40.01 | v181.61,14.61 v173.99,14.61 | v204.47,18.41 207.65,21.59 v224.79,21.59
BUS_CA_06_L  (via drill 0.61)
  Top 0.508: RN4.4 238.76,57.15 238.76,59.69 RN8.4 238.76,62.23 238.76,67.94 J2.PP | v90.17,90.81 90.17,66.04 88.9,64.77 E33.5 | v143.51,94.61 v139.7,90.81 | v171.45,96.52 171.45,72.39 v172.72,71.12
  Bottom 0.508: v139.7,90.81 v90.17,90.81 | v143.51,94.61 144.15,95.25 165.1,95.25 166.37,96.52 v171.45,96.52 | v172.72,71.12 175.26,73.66 243.21,73.66 245.75,71.12 245.75,66.67 241.3,66.67 239.4,68.58 J2.PP
BUS_CA_07_L  (via drill 0.61)
  Top 0.508: v90.17,60.33 90.17,59.69 87,56.52 E33.3 | RN4.7 230.5,56.52 229.87,57.15 229.87,59.69 230.5,60.33 RN8.7 231.14,62.23 231.14,67.94 J2.HH
  Bottom 0.508: v90.17,60.33 182.25,60.33 184.15,62.23 191.77,62.23 192.41,62.87 229.24,62.87 230.5,61.59 RN8.7
BUS_DATA&CLOCK_L  (via drill 0.61)
  Top 0.508: RN4.6 233.68,57.15 233.68,59.69 RN8.6 233.68,62.23 233.68,67.94 J2.KK | v184.78,58.42 184.78,67.94 182.88,69.85 182.88,92.71 E34.3 | v204.47,58.42 v204.47,65.41
  Bottom 0.508: v204.47,58.42 v184.78,58.42 | v204.47,65.41 229.24,65.41 233.04,61.59 RN8.6
BUS_DC_LO_L
  Top 0.508: R50.1 236.85,101.6 238.12,101.6 C53.1 238.76,100.97 240.03,99.69 240.03,85.72 241.3,84.45 J1.TT
BUS_FILE_READY
  Top 0.508: RN1.9 215.9,95.25 215.9,92.71 RN5.9 215.9,90.17 215.9,84.45 J1.V
BUS_HIGH_DENSITY_L
  Top 0.508: RN1.6 208.28,95.25 208.28,92.71 RN5.6 208.28,90.17 208.28,84.45 J1.N
BUS_INDEX_L  (via drill 0.61)
  Top 0.508: J1.Z 220.98,84.45 220.98,90.17 RN6.10 220.98,92.71 220.98,95.25 RN2.10 220.34,97.16 214.63,102.87 203.2,102.87 v203.2,130.18 | 52.07,133.35 57.78,139.06 E11.11 | 52.07,133.35 51.44,132.72 E11.1 | v147.96,130.18 143.51,125.73 143.51,96.52 144.78,95.25 v144.78,85.09 | v63.5,90.81 63.5,94.61 55.24,102.87 52.07,102.87 52.07,133.35
  Bottom 0.508: v147.96,130.18 v203.2,130.18 | v144.78,85.09 143.51,83.82 101.6,83.82 99.69,81.92 95.89,81.92 89.53,88.27 73.03,88.27 70.48,90.81 v63.5,90.81
BUS_READ_GATE_L
  Top 0.508: RN1.5 205.74,95.25 205.74,92.71 RN5.5 205.74,90.17 205.74,84.45 J1.L
BUS_RESTORE_L  (via drill 0.61)
  Top 0.508: RN3.8 210.82,57.15 210.82,59.69 RN7.8 210.82,62.23 210.82,67.94 J2.P | v43.18,59.69 43.18,62.23 38.1,67.31 E22.5 | v245.11,64.14 245.75,64.77 245.75,72.39 242.57,75.56 v242.57,76.2 | v181.61,87 179.07,89.53 v179.07,103.5 | v125.73,103.5 125.73,81.92 120.02,76.2 120.02,65.41 112.39,57.78 110.49,57.78 110.49,47.62 113.67,44.45 v113.67,31.75 | v76.2,29.21 69.22,36.2 v69.22,48.9
  Bottom 0.508: v43.18,59.69 46.99,55.88 47.62,55.88 C34.1 48.9,55.88 51.44,53.34 64.77,53.34 v69.22,48.9 | v245.11,64.14 240.03,64.14 237.49,66.67 213.36,66.67 211.46,68.58 J2.P | v242.57,76.2 239.4,79.38 189.23,79.38 v181.61,87 | v179.07,103.5 170.18,103.5 169.54,102.87 140.97,102.87 140.34,103.5 v125.73,103.5 | v113.67,31.75 111.12,29.21 v76.2,29.21
BUS_RWS_READY_L  (via drill 0.61)
  Top 0.508: v205.74,46.99 205.74,24.77 203.2,22.23 203.2,8.26 197.49,8.26 196.22,9.53 E12.5 | v227.33,46.99 228.6,48.26 228.6,54.61 RN4.8 228.6,57.15 228.6,59.69 RN8.8 228.6,62.23 228.6,67.94 J2.EE
  Bottom 0.508: v227.33,46.99 v205.74,46.99
BUS_SECTOR_ADDR_0L  (via drill 0.61)
  Top 0.508: RN2.8 226.06,95.25 226.06,92.71 RN6.8 226.06,90.17 226.06,84.45 J1.DD | v162.56,127.64 165.1,130.18 165.1,130.81 E6.5 | v201.93,124.46 v201.93,94.61
  Bottom 0.508: R17.1 137.79,127 138.43,127.64 v162.56,127.64 163.83,126.36 200.03,126.36 v201.93,124.46 | v201.93,94.61 224.16,94.61 225.43,95.89 RN2.8
BUS_SECTOR_ADDR_1L  (via drill 0.61)
  Top 0.508: J2.K 205.74,67.94 205.74,62.23 RN7.6 205.74,59.69 205.74,57.15 RN3.6 205.74,54.61 207.01,53.34 v207.01,39.37 | v123.19,126.36 123.19,127.64 121.92,128.91 R18.1 | E6.13 156.84,139.06 156.84,137.79 153.67,137.79 151.13,135.25 151.13,131.44 v144.78,125.09 144.78,116.84 150.5,116.84 153.03,114.3 153.03,110.49 v153.67,109.86 | v187.96,39.37 187.96,60.96 186.06,62.87 v186.06,89.53 | v167,95.25 160.02,102.23 v160.02,106.05
  Bottom 0.508: v123.19,126.36 124.46,125.09 v144.78,125.09 | v207.01,39.37 203.84,36.2 198.12,36.2 194.94,39.37 v187.96,39.37 | v186.06,89.53 183.51,92.08 177.16,92.08 176.53,92.71 176.53,95.25 v167,95.25 | v160.02,106.05 156.21,109.86 v153.67,109.86
BUS_SECTOR_ADDR_2L  (via drill 0.61)
  Top 0.508: J1.FF 228.6,84.45 228.6,90.17 RN6.7 228.6,92.71 228.6,95.25 RN2.7 227.97,97.16 224.16,100.97 224.16,101.6 R16.1 | v168.91,110.49 168.91,111.76 164.47,111.76 160.02,116.2 160.02,125.09 161.29,126.36 161.29,133.35 161.93,133.99 161.93,137.79 162.56,138.43 E6.11
  Bottom 0.508: v168.91,110.49 174.62,104.78 185.42,104.78 189.87,100.33 221.62,100.33 222.88,101.6 R16.1
BUS_SECTOR_ADDR_3L  (via drill 0.61)
  Top 0.508: J1.LL 233.68,84.45 233.68,90.17 RN6.5 233.68,92.71 233.68,95.25 RN2.5 233.04,97.16 231.78,98.42 231.78,99.06 R11.1 231.14,99.69 231.14,120.02 232.41,121.28 v232.41,136.53
  Bottom 0.508: v232.41,136.53 170.81,136.53 168.28,139.06 E6.9
BUS_SECTOR_PULSE_L
  Top 0.508: RN1.8 213.36,95.25 213.36,92.71 RN5.8 213.36,90.17 213.36,84.45 J1.T
BUS_SEEK_INCOMPLETE_L  (via drill 0.61)
  Top 0.508: RN3.4 200.66,57.15 200.66,59.69 RN7.4 200.66,62.23 200.66,67.94 J2.E | v190.5,65.41 189.87,66.04 v189.87,76.2 | v88.9,89.53 83.19,83.82 83.19,72.39 78.74,67.94 v78.74,66.04
  Bottom 0.508: E21.7 51.44,69.22 52.7,70.48 64.77,70.48 66.04,69.22 R27.1 66.67,68.58 69.22,66.04 v78.74,66.04 | v190.5,65.41 198.12,65.41 200.66,67.94 J2.E | v189.87,76.2 184.15,81.92 154.94,81.92 150.5,86.36 144.78,86.36 141.6,89.53 v88.9,89.53
BUS_STROBE_L  (via drill 0.61)
  Top 0.508: v127,82.55 128.27,83.82 v128.27,92.08 | v135.89,110.49 v135.89,92.08 | v186.69,115.57 187.96,114.3 v187.96,90.17 | RN2.3 238.12,95.89 237.49,95.25 237.49,92.71 238.12,92.08 RN6.3 238.76,90.17 238.76,84.45 J1.RR
  Bottom 0.508: v127,82.55 126.36,82.55 122.56,78.74 111.12,78.74 109.86,77.47 64.14,77.47 60.33,81.28 19.05,81.28 19.05,69.22 20.95,67.31 29.21,67.31 34.92,61.59 E22.3 | v135.89,92.08 v128.27,92.08 | v135.89,110.49 141.6,116.2 171.45,116.2 172.09,115.57 v186.69,115.57 | v187.96,90.17 188.59,89.53 236.85,89.53 238.12,90.81 RN6.3
BUS_WP_SET_L
  Top 0.508: RN1.4 203.2,95.25 203.2,92.71 RN5.4 203.2,90.17 203.2,84.45 J1.J
BUS_WP_STATUS_L
  Top 0.508: RN1.7 210.82,95.25 210.82,92.71 RN5.7 210.82,90.17 210.82,84.45 J1.R
BUS_WRITE_CK
  Top 0.508: RN2.6 231.14,95.25 231.14,92.71 RN6.6 231.14,90.17 231.14,84.45 J1.JJ
BUS_WRITE_GATE_L  (via drill 0.61)
  Top 0.508: RN2.9 223.52,95.25 223.52,92.71 RN6.9 223.52,90.17 223.52,84.45 J1.BB | v186.69,105.41 186.69,104.14 185.42,102.87 E34.5
  Bottom 0.508: v186.69,105.41 189.23,102.87 226.69,102.87 227.33,102.23 227.33,98.42 225.43,98.42 224.16,97.16 RN2.9
CA_SW_1  (via drill 0.61)
  Top 0.508: v109.22,106.05 109.22,102.87 E26.9
  Bottom 0.508: v109.22,106.05 111.12,107.95 115.57,107.95 116.84,109.22 118.11,109.22 CYL1.3 120.65,109.22 126.36,109.22 R45.2
CA_SW_2
  Top 0.508: E26.12 100.97,100.97 99.69,99.69 97.79,99.69 97.79,105.41 101.6,109.22 102.87,109.22 CYL2.3
  Bottom 0.508: R44.2 111.12,109.22 105.41,109.22 CYL2.3
CA_SW_4  (via drill 0.61)
  Top 0.508: v135.25,67.31 135.25,90.81 133.35,92.71 v133.35,109.22
  Bottom 0.508: CYL4.3 90.17,109.22 95.89,109.22 R43.2 97.16,109.22 99.69,111.76 104.78,111.76 106.05,113.03 108.58,113.03 109.22,112.39 130.18,112.39 v133.35,109.22 | v135.25,67.31 135.89,66.67 160.02,66.67 160.66,66.04 165.1,66.04 166.37,64.77 166.37,62.23 165.74,61.59 154.31,61.59 153.03,62.87 E27.9
CA_SW_8  (via drill 0.61)
  Top 0.508: v143.51,85.72 143.51,66.04 144.78,64.77 E27.12 | v122.56,88.27 116.84,93.98 116.84,100.97 113.03,104.78 v113.03,124.46 | v78.74,125.73 78.74,114.94 74.3,110.49 CYL8.3
  Bottom 0.508: R42.2 80.64,109.22 74.93,109.22 CYL8.3 | v143.51,85.72 140.97,88.27 v122.56,88.27 | v113.03,124.46 111.76,125.73 v78.74,125.73
CA_SW_16  (via drill 0.61)
  Top 0.508: v110.49,67.31 110.49,66.04 111.76,64.77 E28.9 | v72.39,67.31 72.39,75.56 67.94,80.01 67.94,92.71 66.04,94.61 66.04,108.58 R41.2
  Bottom 0.508: R41.2 65.41,109.22 59.69,109.22 CYL16.3 | v72.39,67.31 v110.49,67.31
CA_SW_32  (via drill 0.61)
  Top 0.508: R40.2 50.16,109.22 44.45,109.22 CYL32.3 | v100.33,74.3 100.33,68.58 104.14,64.77 E28.12 | v78.11,76.2 74.93,79.38 74.93,90.17 72.39,92.71 72.39,95.89 67.31,100.97 67.31,109.86 65.41,111.76 53.34,111.76 v53.34,110.49
  Bottom 0.508: v100.33,74.3 98.42,76.2 v78.11,76.2 | v53.34,110.49 52.07,109.22 51.44,109.22 R40.2
CA_SW_64  (via drill 0.61)
  Top 0.508: v93.98,81.92 93.98,44.45 E29.9 | v65.41,81.92 64.77,82.55 v64.77,110.49
  Bottom 0.508: v65.41,81.92 v93.98,81.92 | v64.77,110.49 63.5,111.76 38.73,111.76 36.2,109.22 R39.2 34.92,109.22 29.21,109.22 CYL64.3
CA_SW_128  (via drill 0.61)
  Top 0.508: v85.09,71.12 85.09,54.61 86.36,53.34 86.36,44.45 E29.12 | v23.5,72.39 22.86,73.03 22.86,96.52 20.32,99.06 20.32,108.58 R38.2
  Bottom 0.508: R38.2 19.68,109.22 13.97,109.22 CYL128.3 | v85.09,71.12 84.45,71.75 36.83,71.75 36.2,72.39 v23.5,72.39
CLOCK_H  (via drill 0.61)
  Top 0.508: v81.28,98.42 81.28,100.33 E7.10 81.28,102.87 81.28,107.31 82.55,108.58 v82.55,127
  Bottom 0.508: v81.28,98.42 72.39,98.42 72.39,102.87 73.03,103.5 74.3,103.5 75.56,102.23 E7.12 | E8.5 136.53,131.44 135.25,130.18 128.91,130.18 127.64,131.44 E8.1 126.36,131.44 122.56,127.64 83.19,127.64 v82.55,127
CONSTANT_WRITE_L  (via drill 0.61)
  Top 0.508: v102.87,141.6 102.87,135.89 100.33,133.35 100.33,126.36 99.06,125.09 99.06,116.2 103.5,111.76 v107.95,111.76 | v117.47,111.12 118.11,111.76 123.19,111.76 v123.19,107.95 | v144.78,107.95 146.69,109.86 146.69,111.76 148.59,113.67 CW.2
  Bottom 0.508: v102.87,141.6 64.77,141.6 64.77,138.43 59.05,132.72 E11.4 | v107.95,111.76 108.58,111.12 v117.47,111.12 | v144.78,107.95 v123.19,107.95
DATA_BITS
  Top 0.508: BIT2.3 224.79,109.22 219.07,109.22 R7.1
  Bottom 0.508: R7.1 217.81,109.22 212.09,109.22 BIT1.3 209.55,109.22 196.85,109.22 BIT0.3 | BIT3.3 240.03,109.86 239.4,110.49 226.69,110.49 BIT2.3
DC_ERASE  (via drill 0.61)
  Top 0.508: v93.34,133.99 88.9,138.43 E10.9 | v124.46,133.99 125.73,132.72 v125.73,123.83 | v136.53,122.56 142.24,116.84 v142.24,114.94
  Bottom 0.508: v124.46,133.99 v93.34,133.99 | v125.73,123.83 127,122.56 v136.53,122.56 | v142.24,114.94 144.78,112.39 158.12,112.39 159.38,113.67 163.83,113.67 DC_ERASE.2
FWD_L  (via drill 0.61)
  Top 0.508: 53.34,84.45 57.78,80.01 FWD/REV.3 | 53.34,84.45 51.44,86.36 R36.1 | v107.31,20.95 109.22,19.05 E17.9 | E16.9 83.82,19.05 85.09,20.32 v85.09,20.95 85.09,31.11 v83.82,32.38 | 53.34,84.45 48.26,79.38 48.26,71.12 46.99,69.85 46.99,41.27 48.26,40.01 v48.26,31.75
  Bottom 0.508: v85.09,20.95 v107.31,20.95 | v48.26,31.75 54.61,31.75 55.24,32.38 v83.82,32.38
GND  (via drill 0.61)
  Top 0.508: CYL16.NC@5 55.88,105.41 CYL16.NC@6 57.78,105.41 59.05,105.41 CYL16.NC@7 60.33,105.41 CYL16.NC@8 | CYL32.NC@8 45.09,105.41 CYL32.NC@7 43.81,105.41 42.55,105.41 CYL32.NC@6 | CYL32.NC@5 40.64,105.41 CYL32.NC@6 | CYL32.NC@6 41.27,107.31 41.27,111.76 42.55,113.03 CYL32.2 42.55,115.57 41.27,116.84 41.27,121.28 CYL32.NC@2 | CYL128.NC@8 14.61,105.41 CYL128.NC@7 13.34,105.41 12.06,105.41 CYL128.NC@6 | CYL128.NC@5 10.16,105.41 CYL128.NC@6 | CYL128.NC@6 10.79,107.31 10.79,111.76 12.06,113.03 CYL128.2 12.06,115.57 10.79,116.84 10.79,121.28 CYL128.NC@2 | CYL32.NC@2 40.64,122.56 CYL32.NC@1 | C11.2 48.26,131.44 46.99,130.18 46.99,125.09 CYL32.NC@3 45.72,122.56 CYL32.NC@4 43.81,121.28 42.55,121.28 CYL32.NC@2 | CYL128.NC@2 10.16,122.56 CYL128.NC@1 | CYL128.NC@2 12.06,121.28 13.34,121.28 CYL128.NC@4 15.24,122.56 CYL128.NC@3 17.14,123.19 23.5,123.19 CYL64.NC@1 25.4,122.56 CYL64.NC@2 27.3,121.28 28.57,121.28 CYL64.NC@4 30.48,122.56 CYL64.NC@3 | E26.7 111.76,92.71 111.76,87.63 POWER.1 | CYL1.NC@8 121.28,105.41 CYL1.NC@7 | CYL1.2 118.11,113.67 116.2,111.76 116.2,106.05 CYL1.NC@5 116.84,105.41 CYL1.NC@6 118.75,105.41 120.02,105.41 CYL1.NC@7 | CYL4.NC@5 86.36,105.41 CYL4.NC@6 | CYL4.NC@6 87,107.31 87,111.76 88.27,113.03 CYL4.2 88.27,115.57 87,116.84 87,121.28 CYL4.NC@2 | CYL2.NC@5 101.6,105.41 CYL2.NC@6 103.5,105.41 104.78,105.41 CYL2.NC@7 106.05,105.41 CYL2.NC@8 | E7.7 86.36,95.25 91.44,100.33 91.44,103.5 CYL4.NC@8 90.81,105.41 CYL4.NC@7 89.53,105.41 88.27,105.41 CYL4.NC@6 | C5.2 121.92,94.61 120.65,95.89 120.65,105.41 CYL1.NC@7 | CYL2.NC@3 106.68,122.56 CYL2.NC@4 104.78,121.28 103.5,121.28 CYL2.NC@2
  Top 0.508: CYL2.NC@2 101.6,122.56 CYL2.NC@1 | CYL2.2 103.5,115.57 102.23,116.84 102.23,121.28 CYL2.NC@2 | CYL1.NC@3 121.92,122.56 CYL1.NC@4 120.02,121.28 118.75,121.28 CYL1.NC@2 116.84,122.56 CYL1.NC@1 116.84,125.09 116.84,130.81 E24.7 116.84,133.35 116.84,135.89 114.3,138.43 E24.9 113.67,139.06 112.39,139.06 E24.10 | E24.13 104.78,139.06 106.05,139.06 E24.12 | CYL4.NC@2 86.36,122.56 CYL4.NC@1 | E10.7 91.44,130.81 91.44,125.09 CYL4.NC@3 91.44,122.56 CYL4.NC@4 89.53,121.28 88.27,121.28 CYL4.NC@2 | CYL8.NC@8 75.56,105.41 CYL8.NC@7 74.3,105.41 73.03,105.41 CYL8.NC@6 | CYL8.NC@5 71.12,105.41 CYL8.NC@6 | CYL8.NC@6 71.75,107.31 71.75,111.76 73.03,113.03 CYL8.2 73.03,115.57 71.75,116.84 71.75,121.28 CYL8.NC@2 | CYL16.NC@2 55.88,122.56 CYL16.NC@1 | CYL16.2 57.78,115.57 56.52,116.84 56.52,121.28 CYL16.NC@2 | CYL8.NC@2 71.12,122.56 CYL8.NC@1 | CYL8.NC@3 76.2,122.56 CYL8.NC@4 74.3,121.28 73.03,121.28 CYL8.NC@2 | E11.7 66.04,130.81 62.23,127 62.23,125.09 CYL16.NC@3 60.96,122.56 CYL16.NC@4 59.05,121.28 57.78,121.28 CYL16.NC@2 | E20.8 33.66,10.16 40.01,10.16 C19.2 40.64,10.79 40.64,11.43 45.72,16.51 E19.15 | C20.2 13.34,10.16 14.61,10.16 E20.1 15.24,11.43 15.24,13.97 17.78,16.51 E20.15 17.78,19.05 22.86,24.13 22.86,34.92 C23.2 | E23.7 40.64,36.83 42.55,38.73 42.55,52.7 C68.- 42.55,53.98 42.55,55.24 38.1,59.69 E22.4 | E32.4 111.76,34.29 112.39,33.66 112.39,19.68 113.03,19.05 113.03,12.7 111.76,11.43 E17.7 | 60.33,14.61 60.96,13.97 60.96,11.43 E19.8 61.59,10.16 67.94,10.16 C16.2 | 60.33,14.61 58.42,16.51 E19.10 | C29.2 78.74,36.2 82.55,40.01 82.55,64.77 81.92,65.41 80.01,65.41 78.74,64.14 C33.2
  Top 0.508: RUN.NC@5 25.4,74.93 RUN.NC@6 27.3,74.93 28.57,74.93 RUN.NC@7 | C22.2 27.94,61.59 27.94,64.77 29.21,66.04 29.21,74.93 RUN.NC@7 | RUN.NC@8 29.84,74.93 RUN.NC@7 | FWD/REV.NC@8 60.33,74.93 FWD/REV.NC@7 | FWD/REV.NC@7 60.33,76.83 60.33,81.28 59.05,82.55 FWD/REV.2 57.78,85.09 56.52,86.36 56.52,90.81 FWD/REV.NC@2 | FWD/REV.NC@7 59.05,74.93 57.78,74.93 FWD/REV.NC@6 55.88,74.93 FWD/REV.NC@5 54.61,73.03 54.61,63.5 55.88,62.23 E21.4 55.88,59.69 55.88,56.52 C34.2 55.88,55.24 55.88,48.9 62.23,42.55 FUNCTION.A 62.87,41.27 62.87,17.14 60.33,14.61 | RTZ.NC@8 45.09,74.93 RTZ.NC@7 43.81,74.93 42.55,74.93 RTZ.NC@6 | RTZ.NC@5 40.64,74.93 RTZ.NC@6 | RTZ.NC@6 41.27,76.83 41.27,81.28 42.55,82.55 RTZ.2 42.55,85.09 41.27,86.36 41.27,90.81 RTZ.NC@2 | CYL64.NC@8 29.84,105.41 CYL64.NC@7 28.57,105.41 27.3,105.41 CYL64.NC@6 | CYL64.NC@6 25.4,105.41 CYL64.NC@5 24.13,103.5 23.5,102.87 23.5,99.69 C60.- 23.5,98.42 24.13,97.79 24.13,94.61 RUN.NC@1 25.4,92.08 RUN.NC@2 27.3,90.81 28.57,90.81 RUN.NC@4 30.48,92.08 RUN.NC@3 | CYL64.2 27.3,113.03 26.04,111.76 26.04,107.31 CYL64.NC@6 | FWD/REV.NC@2 55.88,92.08 FWD/REV.NC@1 53.98,92.71 47.62,92.71 RTZ.NC@3 45.72,92.08 RTZ.NC@4 43.81,90.81 42.55,90.81 RTZ.NC@2 | FWD/REV.NC@3 60.96,92.08 FWD/REV.NC@4 59.05,90.81 57.78,90.81 FWD/REV.NC@2 | RTZ.NC@2 40.64,92.08 RTZ.NC@1 | v168.91,33.66 173.35,33.66 174.62,34.92 E30.4 | E15.12 164.47,17.14 163.19,17.14 E15.13 162.56,19.05 162.56,25.4 160.66,27.3 C67.- | E15.10 170.81,17.14 172.09,17.14 E15.9 172.72,16.51 172.72,13.97 173.35,13.34 | 173.35,13.34 175.26,11.43 E15.7 | 173.35,13.34 170.81,10.79 E15.5 169.54,9.53 168.28,9.53 E15.4 167.64,11.43 167.64,13.97 165.1,16.51 E15.12
  Top 0.508: C30.2 165.1,34.92 165.1,19.05 E15.12 | C41.2 248.28,60.96 247.01,60.96 RN8.1 246.38,59.69 245.11,58.42 245.11,47.62 243.84,46.35 R23.1 | E14.1 210.19,10.16 208.91,10.16 C14.2 | E12.7 200.66,11.43 200.66,13.97 198.12,16.51 E12.9 198.12,19.05 198.12,26.04 196.22,27.94 SECTOR.11 | SECTOR.12 191.13,27.94 195.58,27.94 SECTOR.11 | E13.4 245.75,9.53 244.47,8.26 236.22,8.26 236.22,9.53 C13.2 235.59,10.16 229.24,10.16 E14.8 228.6,11.43 228.6,16.51 E14.9 229.24,17.14 234.95,22.86 D5.A | BIT3.NC@5 238.76,105.41 BIT3.NC@6 240.66,105.41 241.94,105.41 BIT3.NC@7 243.21,105.41 BIT3.NC@8 | C43.2 245.75,91.44 244.47,91.44 RN6.1 | 245.11,103.5 246.38,102.23 C53.2 | 245.11,103.5 BIT3.NC@8 | 245.11,103.5 245.11,92.71 244.47,92.08 RN6.1 | 245.11,103.5 BIT3.NC@8 | BIT2.NC@5 223.52,105.41 BIT2.NC@6 225.43,105.41 226.69,105.41 BIT2.NC@7 227.97,105.41 BIT2.NC@8 | BIT0.NC@5 193.04,105.41 BIT0.NC@6 194.94,105.41 196.22,105.41 BIT0.NC@7 197.49,105.41 BIT0.NC@8 | BIT1.NC@5 208.28,105.41 BIT1.NC@6 210.19,105.41 211.46,105.41 BIT1.NC@7 212.72,105.41 BIT1.NC@8 | CW.NC@1 147.32,122.56 CW.NC@2 149.22,121.28 150.5,121.28 CW.NC@4 152.4,122.56 CW.NC@3 152.4,125.09 152.4,131.44 C6.2 | E8.8 144.78,133.35 144.78,138.43 E8.9 | DC_ERASE.NC@1 162.56,122.56 DC_ERASE.NC@2 164.47,121.28 165.74,121.28 DC_ERASE.NC@4 | E6.7 169.54,132.72 168.28,133.99 166.37,133.99 166.37,123.19 DC_ERASE.NC@4 | DC_ERASE.NC@3 167.64,122.56 DC_ERASE.NC@4 | BIT0.NC@3 198.12,122.56 BIT0.NC@4 196.22,121.28 194.94,121.28 | C2.2 202.56,132.08 196.22,132.08 E4.7 195.58,130.81 193.04,128.27 193.04,125.09 BIT0.NC@1 193.04,122.56 BIT0.NC@2
  Top 0.508: 194.94,121.28 194.94,120.02 BIT0.1 | 194.94,121.28 BIT0.NC@2 | 194.94,121.28 BIT0.NC@2 | BIT3.NC@1 238.76,122.56 BIT3.NC@2 240.66,121.28 240.66,120.02 BIT3.1 241.94,120.02 241.94,121.28 BIT3.NC@4 243.84,122.56 BIT3.NC@3 245.11,125.09 245.11,129.54 246.38,130.81 E1.7 | BIT1.NC@3 213.36,122.56 BIT1.NC@4 211.46,121.28 210.19,121.28 | BIT1.NC@2 208.28,122.56 BIT1.NC@1 | 210.19,121.28 210.19,120.02 BIT1.1 | BIT1.NC@2 210.19,121.28 | BIT1.NC@2 210.19,121.28 | BIT2.NC@1 223.52,122.56 BIT2.NC@2 225.43,121.28 225.43,120.02 BIT2.1 226.69,120.02 226.69,121.28 BIT2.NC@4 228.6,122.56 BIT2.NC@3 228.6,125.09 228.6,131.44 C1.2 | C27.2 137.16,56.52 138.43,57.78 138.43,69.85 139.06,70.48 C61.- | DRIVE.A 125.73,42.55 125.73,54.61 123.19,57.15 120.02,57.15 120.02,56.52 116.2,52.7 114.3,52.7 114.3,54.61 E28.7 | WRITE.NC@5 162.56,74.93 WRITE.NC@6 | WRITE.NC@8 167,74.93 WRITE.NC@7 165.74,74.93 164.47,74.93 WRITE.NC@6 | HEAD.NC@8 151.76,74.93 HEAD.NC@7 150.5,74.93 149.22,74.93 HEAD.NC@6 | HEAD.NC@5 147.32,74.93 HEAD.NC@6 | HEAD.3 149.22,78.11 149.22,76.83 HEAD.NC@6 | WRITE.NC@6 163.19,76.83 163.19,81.28 164.47,82.55 WRITE.2 164.47,85.09 163.19,86.36 163.19,90.81 WRITE.NC@2 | CW.NC@5 147.32,105.41 CW.NC@6 | CW.3 149.22,108.58 149.22,107.31 CW.NC@6 | CW.NC@6 149.22,105.41 150.5,105.41 CW.NC@7 151.76,105.41 CW.NC@8 153.03,103.5 153.03,94.61 HEAD.NC@3 152.4,92.08 HEAD.NC@4 150.5,90.81 149.22,90.81 HEAD.NC@2 147.32,92.08 HEAD.NC@1 | DC_ERASE.NC@5 162.56,105.41 DC_ERASE.NC@6 | DC_ERASE.NC@8 167,105.41 DC_ERASE.NC@7 165.74,105.41 164.47,105.41 DC_ERASE.NC@6 | DC_ERASE.3 164.47,108.58 164.47,107.31 DC_ERASE.NC@6
  Top 0.508: WRITE.NC@2 162.56,92.08 WRITE.NC@1 | WRITE.NC@3 167.64,92.08 WRITE.NC@4 165.74,90.81 164.47,90.81 WRITE.NC@2 | C42.2 193.68,91.44 194.94,91.44 RN5.1 195.58,90.17 195.58,84.45 J1.B 195.58,83.19 195.58,81.92 J1.A 196.22,81.28 197.49,81.28 J1.C 198.75,81.28 200.03,81.28 J1.E 201.29,81.28 202.56,81.28 J1.H 203.84,81.28 205.1,81.28 J1.K 206.38,81.28 207.65,81.28 J1.M 208.91,81.28 210.19,81.28 J1.P 211.46,81.28 212.72,81.28 J1.S 214,81.28 215.26,81.28 J1.U 216.53,81.28 217.81,81.28 J1.W 219.07,81.28 220.34,81.28 J1.Y 221.62,81.28 222.88,81.28 J1.AA 224.16,81.28 225.43,81.28 J1.CC 226.69,81.28 227.97,81.28 J1.EE 229.24,81.28 230.5,81.28 J1.HH 231.78,81.28 233.04,81.28 J1.KK 234.31,81.28 235.59,81.28 J1.MM 236.85,81.28 238.12,81.28 J1.PP 239.4,81.28 240.66,81.28 J1.SS | J1.SS 241.94,81.28 243.21,81.28 J1.UU 243.84,81.92 245.75,83.82 245.75,88.27 243.84,90.17 RN6.1 | J2.B 196.22,71.12 197.49,71.12 J2.D 198.75,71.12 200.03,71.12 J2.F 201.29,71.12 202.56,71.12 J2.J 203.84,71.12 205.1,71.12 J2.L 206.38,71.12 207.65,71.12 J2.N 208.91,71.12 210.19,71.12 J2.R 211.46,71.12 212.72,71.12 J2.T 214,71.12 215.26,71.12 J2.V 216.53,71.12 217.81,71.12 J2.X 219.07,71.12 220.34,71.12 J2.Z 221.62,71.12 222.88,71.12 J2.BB 224.16,71.12 225.43,71.12 J2.DD 226.69,71.12 227.97,71.12 J2.FF 229.24,71.12 230.5,71.12 J2.JJ 231.78,71.12 233.04,71.12 J2.LL 234.31,71.12 235.59,71.12 J2.NN 236.85,71.12 238.12,71.12 J2.RR 239.4,71.12 240.66,71.12 J2.TT | J2.VV 243.21,71.12 241.94,71.12 J2.TT | C40.2 190.5,61.59 188.59,63.5 188.59,67.94 C52.-
  Top 0.508: J1.SS 241.3,80.64 241.3,71.75 J2.TT | C45.+ 175.9,83.19 179.71,79.38 179.71,69.22 C44.- | SECTOR.11 195.58,29.21 193.04,31.75 193.04,53.34 191.77,54.61 191.77,58.42 193.04,59.69 RN7.1 | v95.25,87.63 95.25,59.05 96.52,57.78 96.52,56.52 C28.2
  Bottom 0.508: CYL16.NC@5 53.98,104.14 47.62,104.14 CYL32.NC@8 | CYL32.NC@1 38.73,123.19 32.38,123.19 CYL64.NC@3 | C5.2 121.28,93.98 112.39,93.98 E26.7 | 100.33,85.72 111.12,85.72 POWER.1 | 100.33,85.72 99.69,85.72 POWER_ON.B | E7.7 87,93.98 93.34,93.98 C26.2 | CYL2.NC@5 99.69,104.78 93.34,104.78 CYL4.NC@8 | CYL1.NC@5 114.94,104.14 108.58,104.14 CYL2.NC@8 | E24.12 107.31,140.34 108.58,141.6 109.86,141.6 111.12,140.34 E24.10 | C8.2 123.83,132.08 117.47,132.08 E24.7 | CYL2.NC@3 108.58,123.19 114.94,123.19 CYL1.NC@1 | C24.2 98.42,132.08 92.08,132.08 E10.7 | E11.7 66.67,132.08 73.03,132.08 C10.2 | CYL8.NC@1 69.22,123.19 62.87,123.19 CYL16.NC@3 | CYL4.NC@1 84.45,123.19 78.11,123.19 CYL8.NC@3 | CYL2.NC@1 99.69,123.19 93.34,123.19 CYL4.NC@3 | CYL16.NC@8 62.87,104.14 69.22,104.14 CYL8.NC@5 | E22.4 38.73,60.96 45.09,60.96 C21.2 45.72,60.33 50.16,55.88 55.24,55.88 C34.2 | C23.2 22.86,36.2 24.13,37.47 38.73,37.47 40.01,36.2 E23.7 | E20.8 32.38,10.79 31.11,12.06 23.5,12.06 18.41,17.14 E20.15 | E32.4 111.12,36.2 109.86,37.47 102.87,37.47 101.6,36.2 C32.2 100.97,35.56 97.16,35.56 E29.7 95.89,36.2 93.34,38.73 66.67,38.73 63.5,41.91 FUNCTION.A | E17.7 112.39,10.16 131.44,10.16 C18.2 | C17.2 93.34,10.16 87,10.16 E16.7 85.72,9.53 84.45,8.26 69.85,8.26 68.58,9.53 C16.2 | C7.2 67.94,93.98 62.87,93.98 FWD/REV.NC@3 | RTZ.NC@1 38.73,92.71 32.38,92.71 RUN.NC@3 | RUN.NC@8 32.38,73.66 38.73,73.66 RTZ.NC@5 | C33.2 78.11,63.5 76.2,61.59 56.52,61.59 E21.4 | CYL32.NC@5 38.73,104.14 32.38,104.14 CYL64.NC@8 | v168.91,33.66 166.37,33.66 165.1,34.92 C30.2 164.47,35.56 155.57,35.56 E31.4 154.31,34.92 153.03,33.66 146.05,33.66 144.78,34.92 C31.2
  Bottom 0.508: E18.7 150.5,10.16 156.84,10.16 C15.2 157.48,9.53 158.75,8.26 165.74,8.26 167,9.53 E15.4 | E15.7 175.9,10.16 182.25,10.16 C12.2 182.88,9.53 184.15,8.26 198.75,8.26 200.03,9.53 E12.7 201.29,10.16 207.65,10.16 C14.2 | R70.1 208.91,58.42 209.55,59.05 217.17,59.05 217.81,59.69 222.25,59.69 223.52,58.42 230.5,58.42 R148.1 231.78,58.42 243.84,58.42 245.75,60.33 RN8.1 | SECTOR.11 196.22,27.94 207.65,27.94 C38.2 208.91,27.94 210.19,26.67 221.62,26.67 222.88,25.4 R31.1 224.16,25.4 231.78,25.4 234.31,22.86 234.95,22.86 D5.A 236.85,23.5 237.49,23.5 237.49,41.91 | 237.49,41.91 233.04,41.91 231.78,40.64 C36.2 | 237.49,41.91 239.4,41.91 243.21,45.72 R23.1 | RN6.1 243.21,90.81 241.94,90.81 RN6.2 241.3,92.71 240.66,92.71 239.4,93.98 C39.2 | BIT0.NC@8 200.03,104.14 206.38,104.14 BIT1.NC@5 | BIT2.NC@5 221.62,104.14 215.26,104.14 BIT1.NC@8 | BIT3.NC@5 236.85,104.14 230.5,104.14 BIT2.NC@8 | E6.1 154.31,132.08 153.03,132.08 C6.2 151.76,132.08 145.41,132.08 E8.8 | E6.7 170.81,132.08 177.16,132.08 C4.2 | CW.NC@3 154.31,123.19 160.66,123.19 DC_ERASE.NC@1 | R15.1 183.51,116.84 189.87,123.19 191.13,123.19 BIT0.NC@1 191.13,123.83 169.54,123.83 DC_ERASE.NC@3 | E2.7 221.62,132.08 227.97,132.08 C1.2 | BIT1.NC@3 215.26,123.19 221.62,123.19 BIT2.NC@1 | BIT3.NC@1 236.85,123.19 230.5,123.19 BIT2.NC@3 | BIT0.NC@3 200.03,123.19 206.38,123.19 BIT1.NC@1 | BIT0.NC@6 193.68,107.31 193.68,118.75 194.31,118.75 BIT0.1 | E33.4 89.53,55.88 95.89,55.88 C28.2 96.52,56.52 97.79,57.78 112.39,57.78 113.67,56.52 E28.7 114.3,57.15 126.36,57.15 | 126.36,57.15 135.25,57.15 136.53,55.88 C27.2
  Bottom 0.508: C45.+ 174.62,83.19 166.37,83.19 WRITE.2 | WRITE.NC@5 160.66,73.66 154.31,73.66 HEAD.NC@8 | R14.1 172.09,111.76 168.28,111.76 166.37,109.86 DC_ERASE.3 | CW.NC@8 154.31,104.14 160.66,104.14 DC_ERASE.NC@5 | E5.7 140.34,93.34 145.41,93.34 HEAD.NC@1 | C9.2 174.62,93.98 169.54,93.98 WRITE.NC@3 | HEAD.NC@3 154.31,92.71 160.66,92.71 WRITE.NC@1 | E34.4 186.06,93.34 187.96,91.44 192.41,91.44 C42.2 | 182.88,57.78 182.88,59.69 190.5,59.69 | 182.88,57.78 182.88,57.15 E3.8 | 190.5,59.69 193.04,59.69 RN7.1 | 190.5,59.69 190.5,60.33 C40.2 | 182.88,57.78 163.83,57.78 162.56,56.52 C3.2 161.93,55.88 155.57,55.88 E27.7 154.31,55.24 153.03,53.98 149.22,53.98 148.59,53.34 126.36,53.34 126.36,57.15 | C44.- 180.97,68.58 187.32,68.58 C52.- 188.59,69.22 190.5,71.12 194.94,71.12 J2.B | 100.33,85.72 100.33,87.63 v95.25,87.63
HEAD_SELECT_L  (via drill 0.61)
  Top 0.508: RN1.10 218.44,95.25 218.44,92.71 RN5.10 218.44,90.17 218.44,84.45 J1.X | v158.12,80.64 158.75,81.28 v158.75,96.52
  Bottom 0.508: v158.12,80.64 153.67,80.64 151.13,83.19 HEAD.2 | v158.75,96.52 160.02,97.79 189.87,97.79 194.31,93.34 216.53,93.34 217.81,92.08 RN5.10
N$1
  Bottom 0.508: E12.6 198.75,10.79 200.03,12.06 208.28,12.06 209.55,10.79 209.55,8.26 236.85,8.26 238.12,9.53 E13.1
N$2
  Top 0.508: E7.6 83.82,95.25 82.55,96.52 82.55,107.31 83.82,108.58 83.82,129.54 85.09,130.81 85.09,137.16 86.36,138.43 E10.10
N$3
